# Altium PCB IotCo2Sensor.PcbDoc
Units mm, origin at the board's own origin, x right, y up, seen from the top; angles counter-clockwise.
Board outline 51.5 x 80.5 mm, 2 copper layers (Top Layer, Bottom Layer), stack 1.586 mm thick; 28 components, 17 nets, 100 pads, 13 vias.
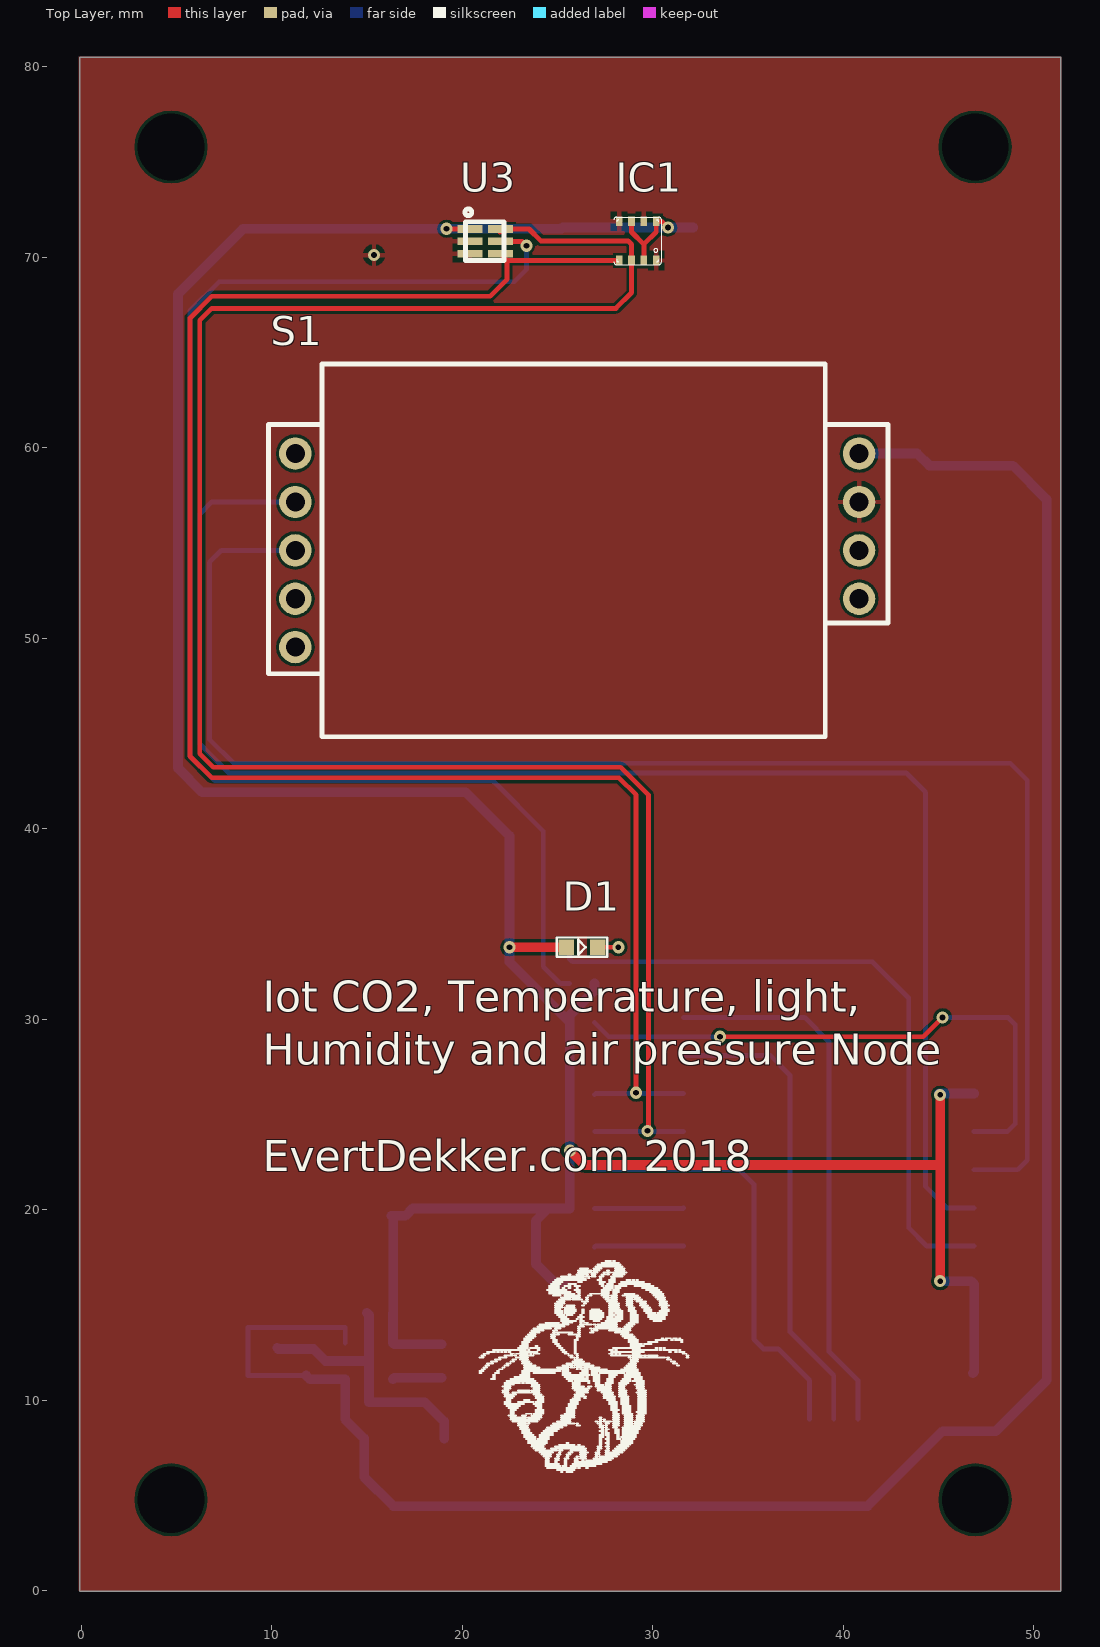
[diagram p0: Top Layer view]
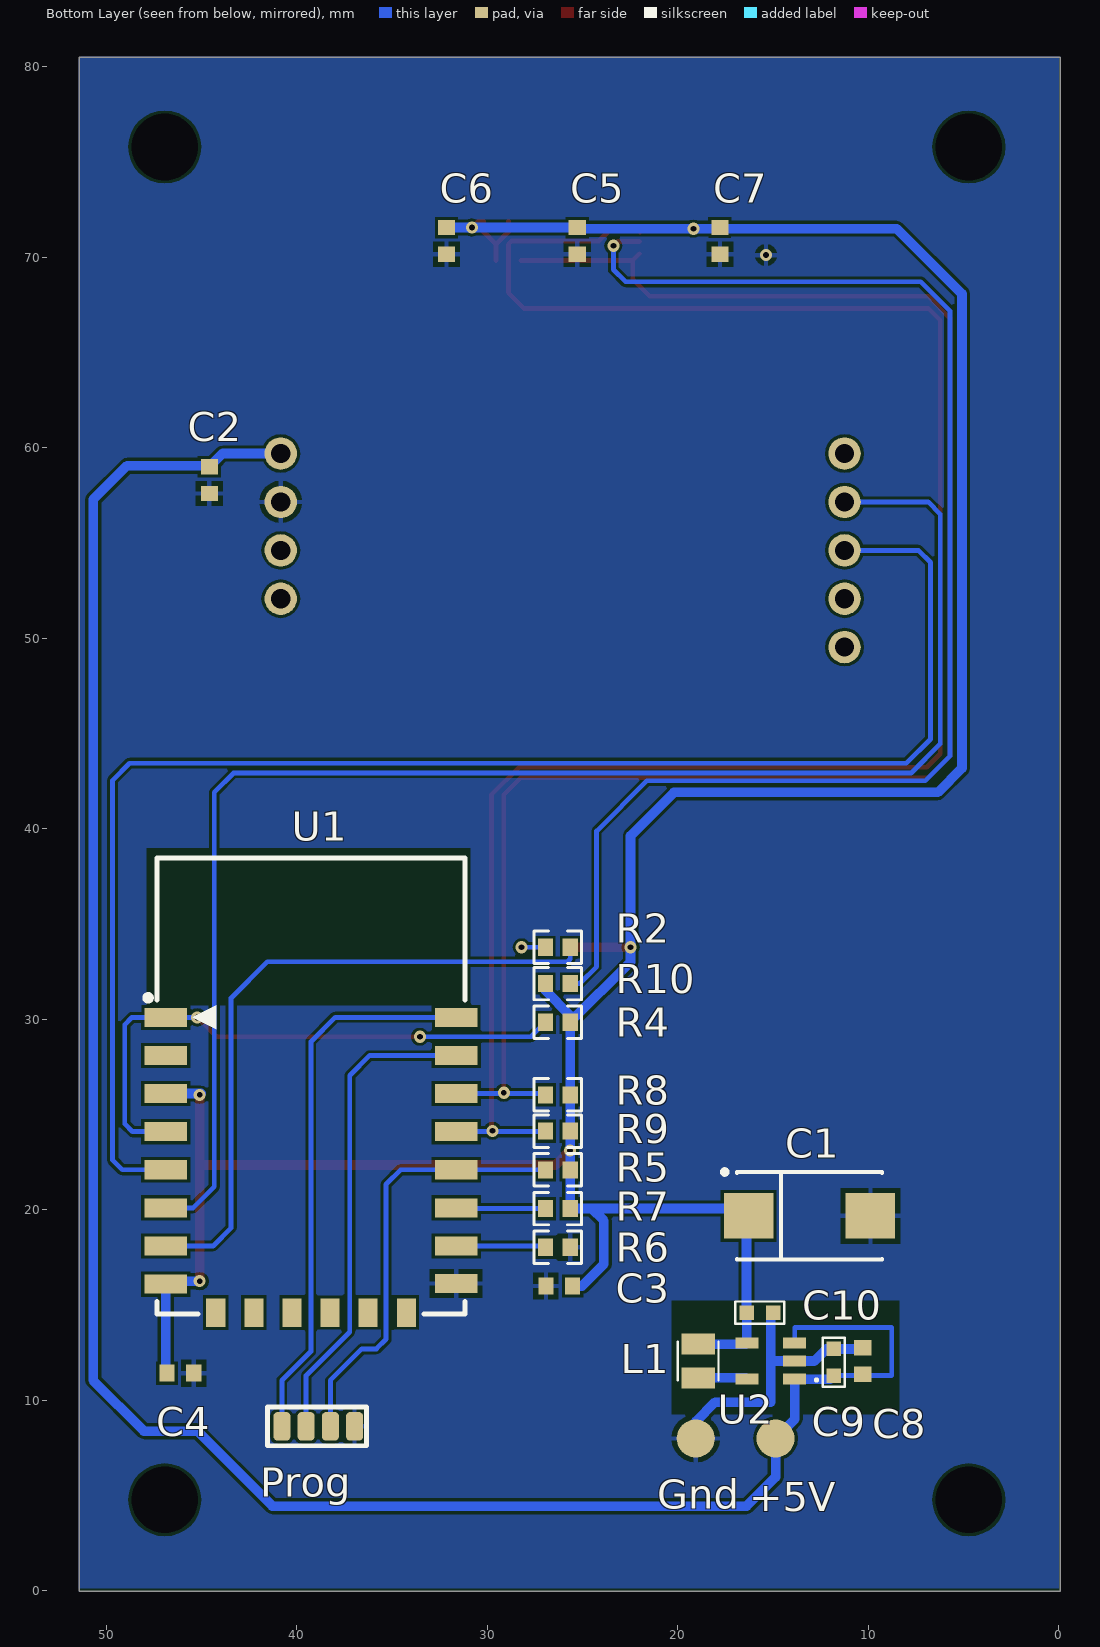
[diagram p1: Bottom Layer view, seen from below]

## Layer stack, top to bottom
Top Solder: solder mask 0.0102, Solder Resist, Dk 3.5
Top Layer: signal copper 0.018
Dielectric1: core 1.55, FR-4, Dk 4.8
Bottom Layer: signal copper 0.018
Bottom Solder: solder mask 0.0102, Solder Resist, Dk 3.5

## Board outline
-0.081,-0.021 -0.081,80.479 51.419,80.479 51.419,-0.021

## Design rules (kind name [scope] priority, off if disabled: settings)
AssemblyTestPointUsage SilkToBoardRegionClearance_1 [All] p2:
Clearance [All] p1: gap=0.152
MatchedLengths DiffPair_DIFF100MatchedLengths [InDifferentialPairClass('DIFF100')] p1: tolerance=0.152 checknetsindiffpair=TRUE checkdiffpairvsdiffpair=FALSE checkxsignals=FALSE checkothers=FALSE
MinimumSolderMaskSliver SilkscreenOverComponentPads_1 [All] p2: minsoldermaskwidth=0.254
MinimumSolderMaskSliver SilkToSolderMaskClearance [IsPad] p3: minsoldermaskwidth=0.254
MinimumSolderMaskSliver SilkscreenOverComponentPads [All] p4: minsoldermaskwidth=0.254
PolygonConnect [All] p1: connectstyle=Relief reliefconductorwidth=0.254 reliefentries=4 polygonreliefangle="90 Angle" airgapwidth=0.254
RoutingVias [All] p1: holewidth=0.305 width=0.635 viastyle="Through Hole" minholewidth=0.305 minwidth=0.635 maxholewidth=0.711 maxwidth=1.27
SilkToSolderMaskClearance SilkToSolderMaskClearance_1 [IsPad] p1: minsilkscreentomaskgap=0.254 clearancetoexposedcopper=TRUE
SolderMaskExpansion [All] p1: expansion=0.102
Width [All] p1: maxlimit=0.508 minlimit=0.152 preferedwidth=0.254 minimp=50.000000 maximp=50.000000 favimp=50.000000
29 further rules are at their usual default settings.

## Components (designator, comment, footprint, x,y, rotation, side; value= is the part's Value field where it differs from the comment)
+5V "Vcc5V" TpSmd2.0 14.859,8.001 r180 bottom (schematic designator TP1)
C1 "T491X" X 13.081,19.685 r180 bottom
C2 "Cap Semi" 1608[0603] 44.577,58.293 r90 bottom
C3 "Cap Semi" 1608[0603] 26.213,16.002 r180 bottom
C4 "Cap Semi" 1608[0603] 46.101,11.43 r0 bottom
C5 "Cap Semi" 1608[0603] 25.273,70.851 r90 bottom
C6 "Cap Semi" 1608[0603] 32.131,70.851 r90 bottom
C7 "Cap Semi" 1608[0603] 17.78,70.851 r90 bottom
C8 "Cap Semi" 1608[0603] 10.287,12.065 r270 bottom
C9 "10uF" 0603C-GENERIC 11.811,11.303 r90 bottom
C10 "10uF" 0603C-GENERIC 16.383,14.605 r180 bottom
D1 "Led" LED1608 26.289,33.782 r0 top
Gnd "Gnd" TpSmd2.0 19.05,8.001 r180 bottom (schematic designator TP2)
IC1 "BME280" BME280 29.21,70.851 r0 top
L1 "4.7uH" INDC2016X100N 18.923,12.065 r90 bottom
Prog "Prog" "Header4x1.27mm SMD" 40.767,8.636 r180 bottom (schematic designator P3)
R2 "Resistor" RES0603R 26.289,33.782 r180 bottom
R4 "Resistor" RES0603R 26.289,29.845 r0 bottom
R5 "Resistor" RES0603R 26.289,22.098 r0 bottom
R6 "Resistor" RES0603R 26.289,18.034 r180 bottom
R7 "Resistor" RES0603R 26.289,20.066 r0 bottom
R8 "Resistor" RES0603R 26.289,26.035 r0 bottom
R9 "Resistor" RES0603R 26.289,24.13 r0 bottom
R10 "Resistor" RES0603R 26.289,31.877 r180 bottom
S1 "MH-Z19" MH-Z19 26.035,54.61 r180 top
U1 "ESP_12_E" ESP_12_E 39.243,22.352 r180 bottom
U2 "PAM2305AAB330" SOT95P280X145-5N 15.113,12.065 r0 bottom
U3 "TSL2561" DFN6-2x2 21.209,70.827 r0 top

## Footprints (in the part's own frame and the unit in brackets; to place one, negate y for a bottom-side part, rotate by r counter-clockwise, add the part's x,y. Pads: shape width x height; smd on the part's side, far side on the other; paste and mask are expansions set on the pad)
0603C-GENERIC [mil] "CAPACITOR 0603"
  rect 30x30 smd: 1(0,0) 2(55,0)
  silkscreen extent -23,-23 78,23, body extent -4,-15 59,15, height 19
1608[0603] [mm] "Chip Capacitor, Body 1.6x0.8mm, IPC High Density"
  rect 0.8x0.9 smd: 1(-0.7,0) 2(0.7,0)
  body extent -0.87,-0.48 0.87,0.48, height 1.3
BME280 [mm]
  rect 0.35x0.5 smd: 1(0.975,-1.025) 2(0.325,-1.025) 3(-0.325,-1.025) 4(-0.975,-1.025) 5(-0.975,1.025) 6(-0.325,1.025) 7(0.325,1.025) 8(0.975,1.025)
  silkscreen extent -1.25,-1.25 1.25,1.25
DFN6-2x2 [mm] "TSL256x Package FN"
  rect 1.3x0.4 smd: 1(-0.8,0.65) 2(-0.8,0) 3(-0.8,-0.65) 4(0.8,-0.65) 5(0.8,0) 6(0.8,0.65)
  silkscreen extent -1.07,-1 0.99,1.7
ESP_12_E [mm] "ESP-12 Wi-Fi Module by AI-Thinker"
  rect 2.25x1 smd: 1(-7.625,7.75) 2(-7.625,5.75) 3(-7.625,3.75) 4(-7.625,1.75) 5(-7.625,-0.25) 6(-7.625,-2.25) 7(-7.625,-4.25) 8(-7.625,-6.25) 15(7.62,-6.223) 16(7.625,-4.25) 17(7.625,-2.25) 18(7.625,-0.25) 19(7.625,1.75) 20(7.625,3.75) 21(7.625,5.75) 22(7.625,7.75)
  rect 1x1.5 smd: 9(-5,-7.75) 10(-3,-7.75) 11(-1,-7.75) 12(1,-7.75) 13(3,-7.75) 14(5,-7.75)
  silkscreen extent -8.7,-7.82 8.08,16.12, body extent -8,-7.74 8,16.26, height 2.75
"Header4x1.27mm SMD" [mm]
  rrect50% 0.9x1.5 smd: 1(0,0) 2(1.27,0) 3(2.54,0) 4(3.81,0)
  silkscreen extent -0.76,-1.02 4.44,1.02
INDC2016X100N [mm]
  rect 1.1x1.77 smd: 1(-0.885,0) 2(0.885,0)
  silkscreen extent -1,-1.06 1,1.06
LED1608 [mm] "1608"
  rect 0.8x0.8 smd: A(-0.826,0) K(0.826,0)
  silkscreen extent -1.33,-0.51 1.33,0.51, body extent -0.8,-0.4 0.8,0.4, height 1.11
MH-Z19 [mm] "MH-Z19 Co2 Ver.1 sensor"
  round 1.7 hole 1: 1(14.795,-5.08) 2(14.795,-2.54) 3(14.795,0) 4(14.795,2.54) 5(14.795,5.08) 6(-14.795,-5.08) 7(-14.795,-2.54) 8(-14.795,0) 9(-14.795,2.54)
  silkscreen extent -16.32,-9.78 16.19,9.78, body extent -16.25,-10 16.32,9.75, height 8.76
RES0603R [mm] "resistor 0603 reflow soldering"
  rect 0.8x0.9 smd: 1(-0.65,0) 2(0.65,0)
  silkscreen extent -1.25,-0.85 1.25,0.85, body extent -0.8,-0.4 0.8,0.4, height 0.45
SOT95P280X145-5N [mm]
  rect 1.21x0.59 smd: 1(-1.255,0.95) 2(-1.255,0) 3(-1.255,-0.95) 4(1.255,-0.95) 5(1.255,0.95)
  silkscreen extent -2.47,0.93 -2.33,1.07, body extent -1.27,-1.5 1.13,1.5, height 1.16
TpSmd2.0 [mm] "TestPointSmd2.0mm"
  round 2 smd paste-2: 1(0,0)
X [mm] "Capacitor, SM Tantalum; Body 7.3 x 4.3 mm (LxW typ)"
  rect 2.6x2.4 smd: 1(-3.2,0) 2(3.2,0)
  silkscreen extent -4.58,-2.3 3.8,2.42

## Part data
+5V Gnd: library part TestPad
C1: "Solid Tantalum Chip Capacitor, Standard T491 Series - Industrial Grade"
C2 C3 C4 C5 C6 C7 C8: "Capacitor (Semiconductor SIM Model)"
C9 C10: library part 0603C-10UF-6V3-X5R-MUR, "CAPACITOR 0603 CERAMIC"
IC1: "Integrated pressure, humidity and temperature sensor; 8-pin 2.5x2.5x0.93mm LGA"
L1: library part LQM2MPN4R7MG0L, "Inductor Power Chip Shielded Multi-Layer 4.7uH 20% 1MHz Ferrite 1.1A 175mOhm DCR 0806 Embossed T/R"
Prog: library part Header4x1.27mm
U1: "ESP-12 Wi-Fi Module by AI-Thinker"

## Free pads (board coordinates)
  round 0 hole 3.5 unplated mask+2: 1(4.719,4.779) 2(46.919,4.779) 3(4.719,75.779) 4(46.919,75.779)

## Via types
v1: diameter 0.635, hole 0.305, Top Layer to Bottom Layer, 13 vias

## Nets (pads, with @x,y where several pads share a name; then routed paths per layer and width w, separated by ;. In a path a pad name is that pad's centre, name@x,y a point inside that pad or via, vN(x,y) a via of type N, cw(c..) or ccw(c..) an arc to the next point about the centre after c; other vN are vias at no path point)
GND: C1.2 C2.1 C3.1 C4.1 C5.1 C6.1 C7.1 C8.1 C9.2 C10.2 Gnd.1 IC1.1 IC1.5 IC1.7 Prog.4 R6.2 S1.7 U1.15 U2.2 U3.2 U3.3 | length 15.1
  Bottom Layer w0.508: C8.1 10.352,12.7 C9.2 12.192,12.7 12.827,12.065 U2.2 15.113,12.065 ; C10.2 15.113,14.478 15.113,12.065 ; Gnd.1 19.05,8.89 18.034,9.906 15.113,9.906 15.113,12.065
  other v1: 15.367,70.104
NetD1_2: D1.K R2.1 | length 2.3
  Top Layer w0.254: D1.K v1(28.194,33.782)
  Bottom Layer w0.254: R2.1 v1(28.194,33.782)
NetL1_1: L1.1 U2.5 | length 2.6
  Bottom Layer w0.508: U2.5 16.433,11.18 L1.1
NetP3_1: Prog.1 U1.22 | length 28.6
  Bottom Layer w0.254: U1.22 37.97,30.102 39.243,28.829 39.243,12.573 40.767,11.049 Prog.1@40.767,9.017
NetP3_2: Prog.2 U1.21 | length 25
  Bottom Layer w0.254: U1.21 36.16,28.102 37.211,27.051 37.211,13.589 39.497,11.303 Prog.2@39.497,9.017
NetP3_3: Prog.3 R5.2 U1.18 | length 22.7
  Bottom Layer w0.254: R5.2 26.943,22.102 U1.18 34.54,22.102 35.306,21.336 35.306,13.208 35.814,12.7 36.576,12.7 38.227,11.049 Prog.3@38.227,9.017
NetR2_2: R2.2 U1.7 | length 35.2
  Bottom Layer w0.254: R2.2 25.639,33.162 25.781,33.02 41.529,33.02 43.434,31.115 43.434,19.05 44.382,18.102 U1.7
NetR4_2: R4.2 U1.1 U1.4 | length 30.5
  Top Layer w0.254: v1(33.528,29.083) 44.196,29.083 v1(45.212,30.099)
  Bottom Layer w0.254: R4.2 27.701,29.083 v1(33.528,29.083) ; v1(45.212,30.099) 45.215,30.102 U1.1 48.638,30.102 49.022,29.718 49.022,24.511 48.613,24.102 U1.4
NetR6_1: R6.1 U1.16 | length 4.7
  Bottom Layer w0.254: R6.1 27.007,18.102 U1.16
NetR7_2: R7.2 U1.17 | length 4.7
  Bottom Layer w0.254: R7.2 31.582,20.066 U1.17
NetR10_2: R10.2 U3.5 | length 73.7
  Top Layer w0.254: U3.5 23.138,70.827 v1(23.368,70.597)
  Bottom Layer w0.254: v1(23.368,70.597) 23.368,69.342 22.733,68.707 7.239,68.707 5.715,67.183 5.715,43.815 7.01,42.52 21.615,42.52 24.257,39.878 24.257,32.766 25.146,31.877 R10.2
NetS1_2: S1.2 U1.6 | length 80.2
  Bottom Layer w0.254: S1.2 6.858,57.15 6.223,56.515 6.223,44.45 7.747,42.926 43.307,42.926 44.323,41.91 44.323,21.209 45.43,20.102 U1.6
NetS1_3: S1.3 U1.5 | length 80.8
  Bottom Layer w0.254: S1.3 7.366,54.61 6.731,53.975 6.731,44.704 8.001,43.434 48.768,43.434 49.657,42.545 49.657,22.606 49.153,22.102 U1.5
SCL: IC1.4 R8.2 U1.20 U3.4 | length 92.5
  Top Layer w0.254: U3.4 22.36,69.826 ; IC1.4 22.36,69.826 ; v1(29.124,26.143) 29.124,41.774 28.226,42.672 6.858,42.672 5.715,43.815 5.715,66.802 6.858,67.945 21.463,67.945 22.36,68.842 22.36,69.826
  Bottom Layer w0.254: R8.2 27.006,26.102 v1@29.083,26.102 ; v1(29.124,26.143) v1@29.083,26.102 ; U1.20 v1@29.083,26.102
SDA: IC1.3 R9.2 U1.19 U3.6 | length 102.9
  Top Layer w0.254: U3.6@21.971,71.439 21.971,71.306 22.009,71.344 U3.6 23.504,71.477 24.13,70.851 28.702,70.851 28.885,70.668 IC1.3 28.885,68.128 28.067,67.31 6.858,67.31 6.223,66.675 6.223,43.942 6.938,43.227 28.321,43.227 29.774,41.774 29.774,24.201 v1(29.718,24.145)
  Bottom Layer w0.254: R9.2@26.967,24.102 v1@29.718,24.102 ; v1(29.718,24.145) v1@29.718,24.102 ; U1.19 v1@29.718,24.102
VCC: C1.1 C3.2 C4.2 C5.2 C6.2 C7.2 C10.1 D1.A IC1.2 IC1.6 IC1.8 L1.2 R4.1 R5.1 R7.1 R8.1 R9.1 R10.1 U1.3 U1.8 U2.4 U3.1 | length 166.6
  Top Layer w0.254: v1(19.177,71.486) 19.186,71.477 U3.1 ; IC1.6 28.885,71.318 29.535,70.668 ; IC1.2 29.535,70.668 ; v1(30.796,71.551) 30.471,71.876 IC1.8 30.185,71.318 29.535,70.668
  Top Layer w0.508: v1(22.479,33.782) D1.A ; v1(25.654,23.114) 26.416,22.352 45.085,22.352 ; v1(45.085,16.256) 45.085,22.352 ; v1(45.085,26.035) 45.085,22.352
  Bottom Layer w0.254: v1(30.796,71.551) v1@30.988,71.551
  Bottom Layer w0.508: C10.1@16.368,14.59 U2.4 16.433,12.95 L1.2 ; C10.1 16.383,19.583 C1.1 17.018,19.685 17.399,20.066 24.511,20.066 ; C3.2 25.019,16.002 23.876,17.145 23.876,19.431 24.511,20.066 ; R10.1 26.939,31.511 25.639,30.211 R4.1 ; v1(30.796,71.551) C5.2 25.208,71.486 v1(19.177,71.486) 8.494,71.486 5.08,68.072 5.08,43.18 6.35,41.91 20.193,41.91 22.479,39.624 v1(22.479,33.782) 22.479,33.005 R4.1 ; v1@30.988,71.551 C6.2 ; v1(45.085,16.256) 46.714,16.256 U1.8 46.868,11.497 C4.2 ; v1(45.085,26.035) 45.018,26.102 U1.3 ; 24.511,20.066 R7.1 R5.1 R9.1 R8.1 R4.1
VCC+5: +5V.1 C2.2 C8.2 C9.1 S1.6 U2.1 U2.3 | length 115.9
  Bottom Layer w0.254: C9.1 8.763,11.303 8.763,13.828 13.858,13.828 U2.3
  Bottom Layer w0.508: C9.1 11.999,11.115 U2.1 13.858,9.002 +5V.1 14.859,5.969 16.383,4.445 41.275,4.445 45.212,8.382 48.006,8.382 50.673,11.049 50.673,57.277 48.895,59.055 44.515,59.055 43.88,59.69 S1.6 S1.6@41.146,59.374
pads on no net: S1.1 S1.4 S1.5 S1.8 S1.9 U1.2 U1.9 U1.10 U1.11 U1.12 U1.13 U1.14

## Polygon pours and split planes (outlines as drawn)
GND on Bottom Layer "GND_L02_P002" (solid, pour order 2): 0,0.127 51.435,0.127 51.435,80.391 51.308,80.518 0,80.518
GND on Top Layer "GND_L01_P004" (solid, pour order 4): -0.127,0 51.435,0 51.435,80.518 -0.127,80.518

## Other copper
Bottom Layer:
  pour cut-out: 30.861,38.989 47.879,38.989 47.879,30.734 30.988,30.734 30.861,30.861
  pour cut-out: 8.382,15.24 20.32,15.24 20.32,9.271 14.558,9.271 8.382,9.271 8.382,12.319

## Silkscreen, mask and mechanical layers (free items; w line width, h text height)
Top Overlay:
  drawing of 667 lines, arcs and shapes, not listed
  text "Iot CO2, Temperature, light, / Humidity and air pressure Node /  / EvertDekker.com 2018" at 9.525,21.463 h2.79
BoardOutline:
  the board outline again, w0.254
Milling:
  lines w0.5: 12.573,64.231 12.573,44.831 39.073,44.831 ; 12.573,64.389 24.384,64.389 24.765,64.77 35.306,64.77 35.687,64.389 39.073,64.389 ; 39.116,44.831 39.116,64.231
